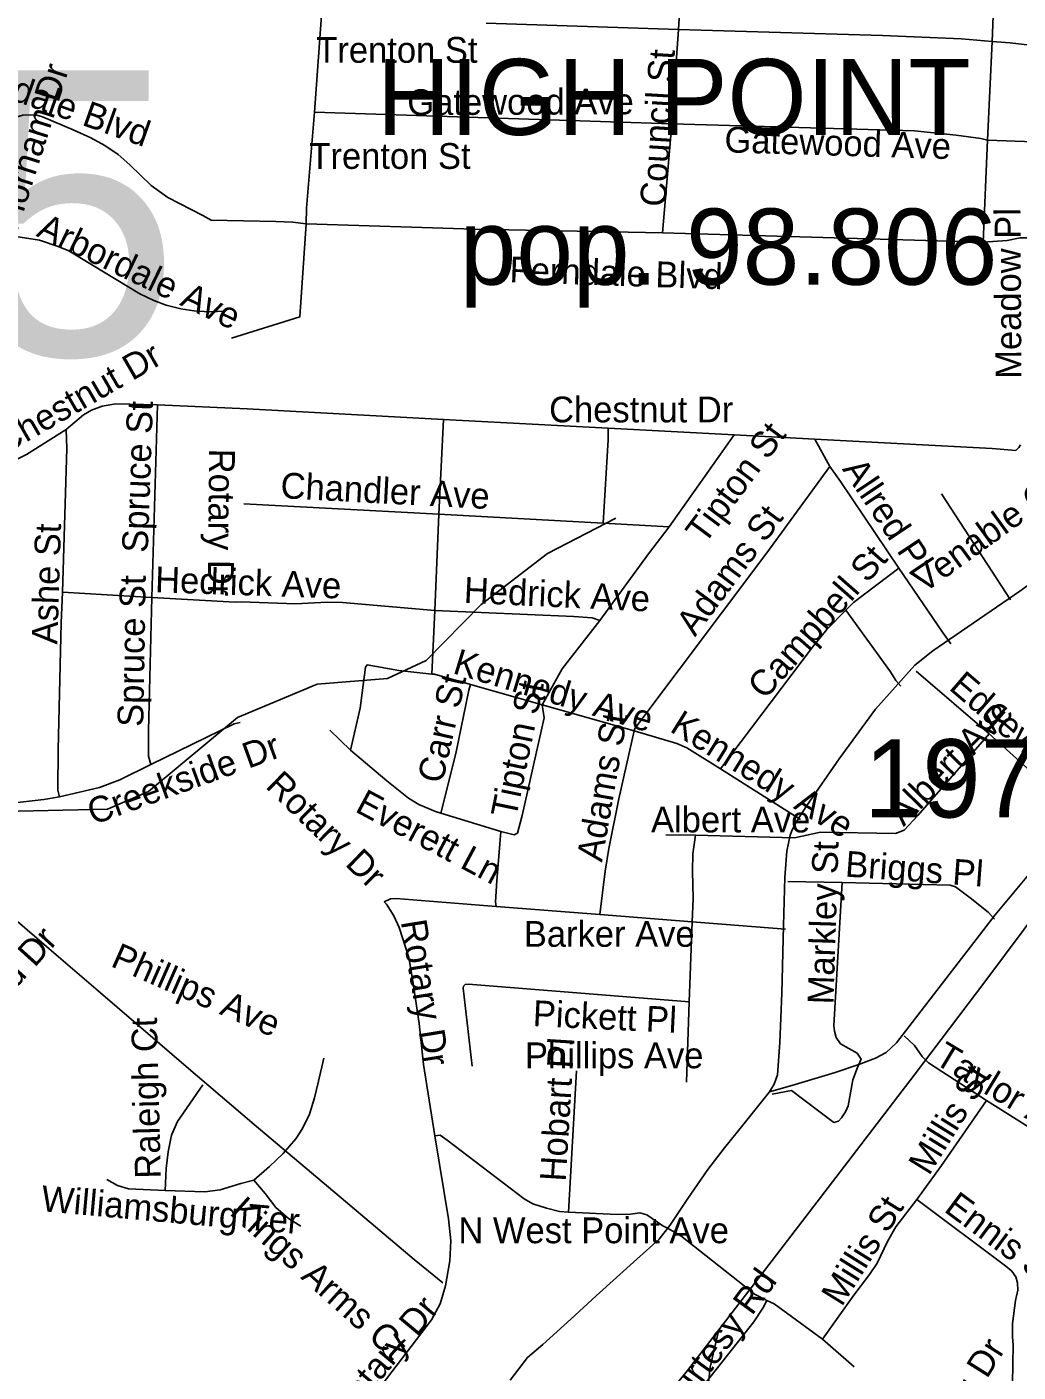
# Model space of a CAD drawing. Extents: x 1662474 to 1856135, y 779280 to 917889.
# Drawn here: x 1695884 to 1699530, y 800984 to 805937 of the extents above; entities that cross this region are included whole.
import ezdxf

# ---------------------------------------------------------------- set-up
doc = ezdxf.new("R2010")
doc.units = 0
for name, color, linetype in [('Cogo Default Point CELL', 7, 'Continuous'), ('Exist Civil Demographics City Label', 7, 'Continuous'), ('Exist Civil Demographics City Population Label', 7, 'Continuous'), ('Exist Hydrographic Misc Water Feature', 7, 'Continuous'), ('Exist Railroad Mainline', 7, 'Continuous'), ('Exist Road Non-System Structure Non-Sys Other Number Label', 7, 'Continuous'), ('Exist Road Non-System Type 51', 7, 'Continuous'), ('Exist Road Non-System Type 51 Label', 7, 'Continuous'), ('Exist Road Secondary Type 51 Attributed', 7, 'Continuous'), ('Exist Road Secondary Type 51 Undivided 4 Lane Attributed', 7, 'Continuous'), ('Exist Utilities Electrical Transmission Line', 7, 'Continuous')]:
    doc.layers.add(name, color=color, linetype=linetype)

msp = doc.modelspace()

# ---------------------------------------------------------------- linework, layer by layer
at = {"layer": 'Exist Hydrographic Misc Water Feature'}
msp.add_lwpolyline([(1692993.9, 802914.1), (1693385.8, 802896.4), (1693468.9, 802911.1), (1693684.9, 802873.8), (1694219.9, 802928.6), (1694387.8, 803059.8), (1694812.9, 803080.7), (1694912.8, 803111.4), (1695137.9, 803110.2), (1695337.9, 803040.6), (1695412.9, 803039), (1696179.9, 803056.2), (1696330.9, 803122.1), (1696658.9, 803394.4), (1696951.9, 803516.5), (1697209.9, 803537.5), (1697352.9, 803603.5), (1697554.9, 803809.5), (1697799, 803998.2), (1698049.9, 804127.7)], dxfattribs=at)
at = {"layer": 'Exist Railroad Mainline'}
for points in [[(1695532.7, 797355.6), (1695836.9, 797740.1), (1696137.3, 798128.2), (1696366.8, 798424.8), (1696552.5, 798677.8), (1696687.5, 798856.9), (1696858.6, 799090), (1697171.2, 799514.3), (1697410.9, 799824.9), (1697668.8, 800159.4), (1697920.8, 800480.2), (1698160.7, 800801), (1698313.9, 800989.9), (1698585.6, 801342.5), (1698859.8, 801700.9), (1699147.7, 802077.2), (1699411.8, 802426), (1699690.2, 802798.4)], [(1698378.2, 800731.6), (1698380.9, 800831.6), (1698397.8, 801001.6), (1698426.4, 801129.4)]]:
    msp.add_lwpolyline(points, dxfattribs=at)
at = {"layer": 'Exist Road Non-System Type 51'}
for p, q in [((1698280.4, 805926.9), (1698315.2, 806447.1)), ((1696941.5, 805623.2), (1696971.6, 806030.2)), ((1698280.4, 805926.9), (1697573, 805950.5)), ((1698256.9, 805580.2), (1698280.4, 805926.9)), ((1699417.6, 805519.2), (1699434.9, 805882.8)), ((1698256.9, 805580.2), (1696941.5, 805623.2)), ((1698222.1, 805178.1), (1698256.9, 805580.2)), ((1699402.4, 805143.9), (1699417.6, 805519.2)), ((1699402.4, 805143.9), (1698222.1, 805178.1)), ((1696343.4, 803836.1), (1696363.6, 804545.2)), ((1696694.2, 804530.1), (1696363.6, 804545.2)), ((1697416.6, 804490.7), (1696694.2, 804530.1)), ((1697399.2, 804142.1), (1697416.6, 804490.7)), ((1698022.1, 804459.2), (1697416.6, 804490.7)), ((1698486.1, 804434.5), (1698022.1, 804459.2)), ((1698486.1, 804434.5), (1698246.8, 804095.9)), ((1698783.1, 804418.2), (1698486.1, 804434.5)), ((1698837.2, 804318), (1698783.1, 804418.2)), ((1699502.9, 803826.9), (1699249.1, 804218)), ((1697399.2, 804142.1), (1696681.6, 804180.4)), ((1697384.2, 803787.5), (1697399.2, 804142.1)), ((1698003.6, 804109.4), (1697399.2, 804142.1)), ((1698246.8, 804095.9), (1698003.6, 804109.4)), ((1696343.4, 803836.1), (1696015, 803855.5)), ((1697373, 803553.9), (1697384.2, 803787.5)), ((1699423.9, 803333.8), (1699155.4, 803564.4)), ((1697779, 803441.1), (1697516.2, 803515.1)), ((1698118.4, 803345), (1697779, 803441.1)), ((1697074.4, 803274.2), (1696997.6, 803347.4)), ((1698729.4, 803018.5), (1698435.6, 803205.4)), ((1697627.6, 802974.2), (1697406.1, 803042.2)), ((1698343.4, 802960.5), (1698234.1, 802962.4)), ((1698707.9, 802951.6), (1698343.4, 802960.5)), ((1698883.4, 802786), (1698682.9, 802789.9)), ((1697991.9, 802668.2), (1697610, 802698.4)), ((1698331.2, 802641.7), (1697991.9, 802668.2)), ((1698331.2, 802641.7), (1698320.5, 802346.9)), ((1698674.2, 802614.6), (1698331.2, 802641.7)), ((1698320.5, 802346.9), (1698310.5, 802051.9)), ((1697384.5, 801854.5), (1697342.2, 802116.4)), ((1697905.8, 802093.6), (1697876.6, 801572.6)), ((1699632.5, 801846.4), (1699413.9, 801984.4)), ((1698810.5, 801105.7), (1698926.8, 801003.6))]:
    msp.add_line(p, q, dxfattribs=at)
for points in [[(1699434.9, 805882.8), (1699445.4, 806135), (1699445.6, 806222.9), (1699451.1, 806284.4)], [(1699434.9, 805882.8), (1699322.2, 805893), (1699031.2, 805905.4), (1698280.4, 805926.9)], [(1699812.9, 805841.1), (1699501.9, 805878.4), (1699434.9, 805882.8)], [(1696911.6, 805211.9), (1696912.4, 805269.7), (1696941.5, 805623.2)], [(1696530.2, 805241.6), (1696402.6, 805308.2), (1696340.1, 805352.4), (1696262, 805429), (1696219.5, 805466.2), (1696170.4, 805499.6), (1696119.1, 805527.9), (1696053.6, 805557.9), (1695940.5, 805604.9), (1695919.5, 805611.4), (1695897.6, 805613.2), (1695868.9, 805611.4), (1695847.2, 805605.4)], [(1699417.6, 805519.2), (1699393.1, 805525.4), (1699302.1, 805538.2), (1699149.6, 805553.4), (1698256.9, 805580.2)], [(1699985.5, 805615.4), (1699860.1, 805527.2), (1699833.6, 805515.1), (1699808.1, 805508.2), (1699792.6, 805506.4), (1699417.6, 805519.2)], [(1696911.6, 805211.9), (1696862, 805217.4), (1696799.8, 805220.1), (1696561.8, 805225.1), (1696530.2, 805241.6)], [(1696612.1, 804889.6), (1696554.9, 804887.5), (1696497.4, 804891.2), (1696450.4, 804898), (1696395.4, 804912.4), (1696350.9, 804928.8), (1696299.2, 804953.7), (1696038.1, 805111.7), (1695999, 805128.4), (1695929.4, 805151), (1695690.1, 805188)], [(1696636, 804790.2), (1696888.2, 804869.7), (1696911.6, 805211.9)], [(1698222.1, 805178.1), (1697530.1, 805191.8), (1696911.6, 805211.9)], [(1699563.8, 805160.2), (1699538.6, 805160.2), (1699490, 805150), (1699402.4, 805143.9)], [(1696363.6, 804545.2), (1696210.9, 804549.2), (1696160.9, 804540.2), (1696121.4, 804525.1), (1696091.9, 804508.2), (1696027.6, 804453.9)], [(1696027.6, 804453.9), (1695881.9, 804362.6), (1695801.6, 804321.7), (1695718.1, 804284.7), (1695678.2, 804272.6)], [(1696015, 803855.5), (1696030.5, 804384.1), (1696027.6, 804453.9)], [(1698003.6, 804109.4), (1698022.1, 804416.9), (1698022.1, 804459.2)], [(1699539.1, 804397.8), (1699533.1, 804388.1), (1699521.8, 804377.6), (1699435.4, 804383.9), (1698783.1, 804418.2)], [(1698837.2, 804318), (1698606.4, 804000.7), (1698120.2, 803353.2), (1698118.4, 803345)], [(1699091.1, 803943.7), (1698876.9, 804263.1), (1698837.2, 804318)], [(1698246.8, 804095.9), (1698170.9, 803997), (1697991.4, 803751.1)], [(1699091.1, 803943.7), (1698924.6, 803816.9), (1698896.4, 803789.7)], [(1699283.4, 803665.8), (1699252.2, 803707.8), (1699091.1, 803943.7)], [(1696003.1, 803102.2), (1695996.9, 803126.9), (1695998.8, 803275.2), (1696010, 803742.4), (1696015, 803855.5)], [(1696339.4, 803221.2), (1696330.8, 803251.6), (1696330.8, 803345.2), (1696343.4, 803836.1)], [(1696671.4, 803819.9), (1696649.6, 803818.8), (1696343.4, 803836.1)], [(1697384.2, 803787.5), (1697044.1, 803816.9), (1696988.2, 803818.2), (1696872.1, 803812.5), (1696671.4, 803819.9)], [(1698896.4, 803789.7), (1698826.2, 803718.5), (1698773.8, 803652.9), (1698435.6, 803205.4)], [(1699098.9, 803509.9), (1699080.4, 803530.1), (1699060.6, 803561.6), (1698896.4, 803789.7)], [(1697991.4, 803751.1), (1697963, 803761), (1697895.6, 803765.5), (1697384.2, 803787.5)], [(1697991.4, 803751.1), (1697853, 803573.4), (1697779, 803441.1)], [(1697373, 803553.9), (1697252.5, 803566.9), (1697135.4, 803587.9), (1697128.9, 803579.2), (1697109.8, 803428.2), (1697074.4, 803274.2)], [(1697516.2, 803515.1), (1697382.9, 803553.7), (1697373, 803553.9)], [(1697406.1, 803042.2), (1697461.1, 803261), (1697510, 803494.7), (1697516.2, 803515.1)], [(1697779, 803441.1), (1697786.9, 803392.9), (1697705.2, 803033), (1697688.1, 802968.4), (1697675.9, 802962.4), (1697627.6, 802974.2)], [(1696667.8, 803375.8), (1696646, 803370.8), (1696339.4, 803221.2)], [(1698118.4, 803345), (1698060.9, 803094.1), (1698025.1, 802911.4), (1698011, 802828.2), (1697991.9, 802668.2)], [(1698435.6, 803205.4), (1698311.9, 803282), (1698275.1, 803298.1), (1698118.4, 803345)], [(1699423.9, 803333.8), (1699162.1, 803033.2), (1699111, 802979.7), (1699078.8, 802967.1), (1698803.9, 802971.6), (1698707.9, 802951.6)], [(1699763.5, 803037.4), (1699588.9, 803185.4), (1699423.9, 803333.8)], [(1697406.1, 803042.2), (1697386.6, 803047.4), (1697325.8, 803073.4), (1697287.9, 803096.5), (1697207.4, 803161), (1697074.4, 803274.2)], [(1696339.4, 803221.2), (1696225.5, 803165), (1696150.1, 803136.7), (1696003.1, 803102.2)], [(1696003.1, 803102.2), (1695946, 803092.2), (1695859.4, 803081.8), (1695764.6, 803080.8), (1695669.4, 803084.7), (1695640.8, 803078.7)], [(1697627.6, 802974.2), (1697612.4, 802792.9), (1697607.6, 802715.9), (1697610, 802698.4)], [(1698343.4, 802960.5), (1698333.6, 802891.5), (1698332.2, 802828.2), (1698334.9, 802728.2), (1698331.2, 802641.7)], [(1698883.4, 802786), (1698851.9, 802259.5), (1698854.4, 802238.8), (1698861.6, 802215.9), (1698877.4, 802192.4), (1698938.6, 802158.2), (1698952.5, 802136.4), (1698939.6, 802105.2)], [(1699443.6, 802651.9), (1699420.8, 802676.9), (1699354.1, 802730.6), (1699300, 802770.8), (1699281.1, 802776.2), (1698883.4, 802786)], [(1697610, 802698.4), (1697242, 802727.2), (1697221.2, 802726.9), (1697197.9, 802715.7)], [(1697342.2, 802116.4), (1697326.2, 802267.6), (1697302.6, 802430.6), (1697288.5, 802510.4), (1697253, 802620.9), (1697233.4, 802663.7), (1697206.6, 802706.4), (1697197.9, 802715.7)], [(1697521.2, 802110.9), (1697488.8, 802397.2), (1697490, 802405.2), (1697496.4, 802410.7), (1697507.9, 802412.2), (1698320.5, 802346.9)], [(1699413.9, 801984.4), (1699201.4, 802123.2), (1699177.4, 802146.1), (1699149.6, 802186), (1699111.5, 802221.9)], [(1696975.6, 802139.9), (1696957, 802054.8), (1696942.2, 801993.6), (1696923.4, 801933.5), (1696898.1, 801881), (1696873.2, 801842.4), (1696826.9, 801788.9), (1696775.6, 801741.4), (1696718.9, 801691)], [(1698939.6, 802105.2), (1698922.4, 802060.5), (1698904.8, 801964.5), (1698895.5, 801942.2), (1698881.1, 801919.6), (1698869.9, 801907.5), (1698852.2, 801903.4), (1698696.9, 802021.4), (1698625.1, 802007.5)], [(1696391.9, 801652.7), (1696396.1, 801734), (1696403.4, 801794.4), (1696415, 801855.9), (1696438.1, 801906.2), (1696530.2, 802041.4)], [(1699413.9, 801984.4), (1699248.5, 801745.1), (1699158.2, 801619.9)], [(1697384.5, 801854.5), (1697434.4, 801548.2), (1697443.4, 801467.1), (1697439.9, 801393.9), (1697424.1, 801301.2), (1697404.2, 801235.6), (1697372.1, 801176.9), (1696729.4, 800333.9)], [(1697876.6, 801572.6), (1697843.1, 801575.8), (1697795, 801587.1), (1697744.4, 801604.1), (1697712.6, 801622.5), (1697429.9, 801837.7), (1697403.6, 801855.9), (1697384.5, 801854.5)], [(1696391.9, 801652.7), (1696256.8, 801659), (1696216.9, 801670.5), (1696178, 801693.4)], [(1696718.9, 801691), (1696670.6, 801678.9), (1696594.2, 801654.8), (1696537.6, 801647.4), (1696391.9, 801652.7)], [(1696890.9, 801521.4), (1696846, 801549), (1696799.5, 801589.7), (1696759.9, 801641.1), (1696718.9, 801691)], [(1699158.2, 801619.9), (1699080.4, 801518.6), (1699049.4, 801464.8), (1699011.5, 801384.7), (1698984, 801343.5), (1698925.8, 801266.9), (1698810.5, 801105.7)], [(1699158.2, 801619.9), (1699485.2, 801374.5), (1699507.1, 801355.9), (1699522, 801334.4), (1699528.9, 801312.2), (1699529.9, 801286.2), (1699520.8, 801247.4), (1699509.4, 801162.7), (1699509.6, 801112.2), (1699512.9, 801083.9), (1699509.6, 800941.7)], [(1698242.8, 801512.2), (1698223.1, 801522), (1698164.6, 801562.9), (1698138.4, 801570.2), (1698103.9, 801565.5), (1698055.6, 801564.2), (1697876.6, 801572.6)], [(1698605.8, 801247.7), (1698560.6, 801271.4), (1698522.9, 801301.5), (1698289.5, 801486.2), (1698242.8, 801512.2)], [(1698605.8, 801247.7), (1698591.1, 801219.1), (1698558, 801169.5), (1698382.6, 800946.4)], [(1698605.8, 801247.7), (1698632.9, 801235.9), (1698810.5, 801105.7)]]:
    msp.add_lwpolyline(points, dxfattribs=at)
at = {"layer": 'Exist Road Secondary Type 51 Attributed'}
for points in [[(1701983.5, 805585.5), (1701835.7, 805477.7), (1701639.5, 805344.7), (1701467.7, 805214.3), (1701197.7, 805043.2), (1701022.7, 804911.8), (1700424.7, 804499.7), (1699537.1, 803858.8), (1699217.3, 803639.4), (1699150.4, 803587.1), (1699006.3, 803424.8), (1698871.9, 803242.2), (1698753.2, 803069.5), (1698715.2, 803011.3), (1698698.7, 802980), (1698691.6, 802961.2), (1698679.8, 802902.2), (1698672.2, 802805.5), (1698667.8, 802628.5), (1698660.9, 802379), (1698653.9, 802197.5), (1698644.8, 802078.9), (1698633.3, 802044.4), (1698615.7, 802015.4)], [(1698615.7, 802015.4), (1698698.2, 802039.4), (1698857.4, 802087.6), (1698944.3, 802116.6), (1699005.4, 802139.8), (1699045, 802161.2), (1699082.8, 802195.8), (1699445.8, 802668.1), (1699660.8, 802925)]]:
    msp.add_lwpolyline(points, dxfattribs=at)
at = {"layer": 'Exist Road Secondary Type 51 Undivided 4 Lane Attributed'}
msp.add_lwpolyline([(1697661.7, 800953.8), (1697725.5, 801037.5), (1697781.3, 801085.3), (1697884.9, 801178.9), (1697978.5, 801264.5), (1698128, 801399.9), (1698209.7, 801473.6), (1698249.5, 801523.4), (1698315.3, 801623), (1698389, 801730.5), (1698450.8, 801810.2), (1698517.1, 801892.6), (1698615.7, 802015.4)], dxfattribs=at)
at = {"layer": 'Exist Utilities Electrical Transmission Line'}
msp.add_lwpolyline([(1690667, 807073.7), (1690933.6, 806848.3), (1691312.5, 806526.5), (1691736.7, 806164.4), (1692143.2, 805812.4), (1692470, 805535), (1692830.7, 805223.1), (1693263.3, 804850.9), (1693594.2, 804579.3), (1693733.4, 804448.4), (1694040.2, 804189.1), (1694380.9, 803897.6), (1694775.8, 803555.4), (1695108.4, 803273.9), (1695295.6, 803112.9), (1695566.6, 802881.6), (1695706.3, 802764.8), (1695999.3, 802513.4), (1696154.8, 802380.9), (1696469.3, 802109.3), (1696720.3, 801895.7), (1697055.3, 801612.2), (1697308.3, 801399), (1697413.9, 801312.5)], dxfattribs=at)

# ---------------------------------------------------------------- texts
at = {"layer": 'Cogo Default Point CELL'}
msp.add_text('1970', height=288, dxfattribs=at).set_placement((1698964, 803026))
at = {"layer": 'Exist Civil Demographics City Label'}
msp.add_text('HIGH POINT', height=280, dxfattribs=at).set_placement((1697171.4, 805538.7))
at = {"layer": 'Exist Civil Demographics City Population Label'}
msp.add_text('pop. 98.806', height=280, dxfattribs=at).set_placement((1697476.1, 804987.5))
at = {"layer": 'Exist Road Non-System Structure Non-Sys Other Number Label'}
msp.add_text('J405', height=1049.86, dxfattribs=at).set_placement((1693402.7, 804727.4))
at = {"layer": 'Exist Road Non-System Type 51 Label'}
for s, p in [('Trenton St', (1696948.3, 805804.4)), ('Trenton St', (1696922.8, 805413.8)), ('Chestnut Dr', (1697804.8, 804480.6)), ('Albert Ave', (1698179.9, 802970.9)), ('Barker Ave', (1697711.9, 802549.9)), ('Phillips Ave', (1697716.1, 802102.6)), ('N West Point Ave', (1697471.1, 801458.5))]:
    msp.add_text(s, height=95, dxfattribs=at).set_placement(p)
for s, rotation, p in [('Ferndale Blvd', 340.3862, (1695576.5, 805756.7)), ('Council St', 86.6355, (1698234.1, 805272.5)), ('Florham Dr', 72.3593, (1695846.9, 805176.9)), ('Gatewood Ave', 0.2365, (1697283.3, 805611.6)), ('Gatewood Ave', 358.2688, (1698449, 805474.9)), ('Arbordale Ave', 334.3265, (1695914.4, 805167.9)), ('Meadow Pl', 90.3243, (1699542.8, 804641.3)), ('Ferndale Blvd', 358.1091, (1697658.3, 804996.4)), ('Chestnut Dr', 30.0474, (1695800.6, 804360)), ('Spruce St', 88.0161, (1696328.2, 803999.6)), ('Tipton St', 53.2363, (1698376.7, 804027.7)), ('Rotary Dr', 269.5146, (1696554, 804384)), ('Chandler Ave', 356.9932, (1696815, 804201.8)), ('Allred Pl', 303.7321, (1698881.3, 804308.3)), ('Venable Ct', 35.895, (1699183, 803848.8)), ('Adams St', 53.3405, (1698341.7, 803688.4)), ('Ashe St', 88.2241, (1695995.5, 803662.2)), ('Campbell St', 48.6806, (1698598.5, 803456.3)), ('Hedrick Ave', 358.0239, (1696354, 803855.5)), ('Spruce St', 89.0594, (1696311.6, 803359)), ('Hedrick Ave', 357.2771, (1697489.8, 803816.7)), ('Kennedy Ave', 343.1324, (1697446.5, 803557.9)), ('Carr St', 77.3339, (1697412.3, 803147.6)), ('Edgeworth St', 319.2516, (1699272.2, 803499.8)), ('Tipton St', 78.3011, (1697682.9, 803019.7)), ('Albert Ave', 45.5411, (1699109.3, 802990)), ('Adams St', 80.0572, (1697999.4, 802859.4)), ('Kennedy Ave', 328.1192, (1698244.9, 803344.9)), ('Creekside Dr', 19.9935, (1696127.5, 802997.3)), ('Rotary Dr', 315.6702, (1696757.7, 803137.8)), ('Everett Ln', 331.8818, (1697086.6, 803049.6)), ('Markley St', 88.1732, (1698850.9, 802336.9)), ('Briggs Pl', 355.748, (1698892.1, 802808.7)), ('Edgewood Dr', 47.9193, (1695485.6, 801999.4)), ('Rotary Dr', 279.2607, (1697258.7, 802642.8)), ('Phillips Ave', 336.2641, (1696187.9, 802479.8)), ('Pickett Pl', 357.2215, (1697743.4, 802258.3)), ('Raleigh Ct', 91.4154, (1696376.5, 801697.3)), ('Hobart Pl', 86.4396, (1697865.7, 801684.2)), ('Taylor Ave', 328.8881, (1699217.1, 802123.3)), ('Millis St', 58.282, (1699202.5, 801704.2)), ('Williamsburg Ter', 354.8952, (1695933.3, 801576.8)), ('Kings Arms Ct', 318.0776, (1696625.2, 801567.1)), ('Millis St', 58.0618, (1698881.7, 801221.7)), ('Ennis St', 323.3463, (1699253.9, 801577.8)), ('Courtesy Rd', 53.7623, (1698229.9, 800750.3)), ('Rotary Dr', 50.1655, (1697055.3, 800796.7)), ('Redding Dr', 57.8044, (1699144.7, 800526.3))]:
    msp.add_text(s, height=95, rotation=rotation, dxfattribs=at).set_placement(p)

doc.saveas('drawing.dxf')
